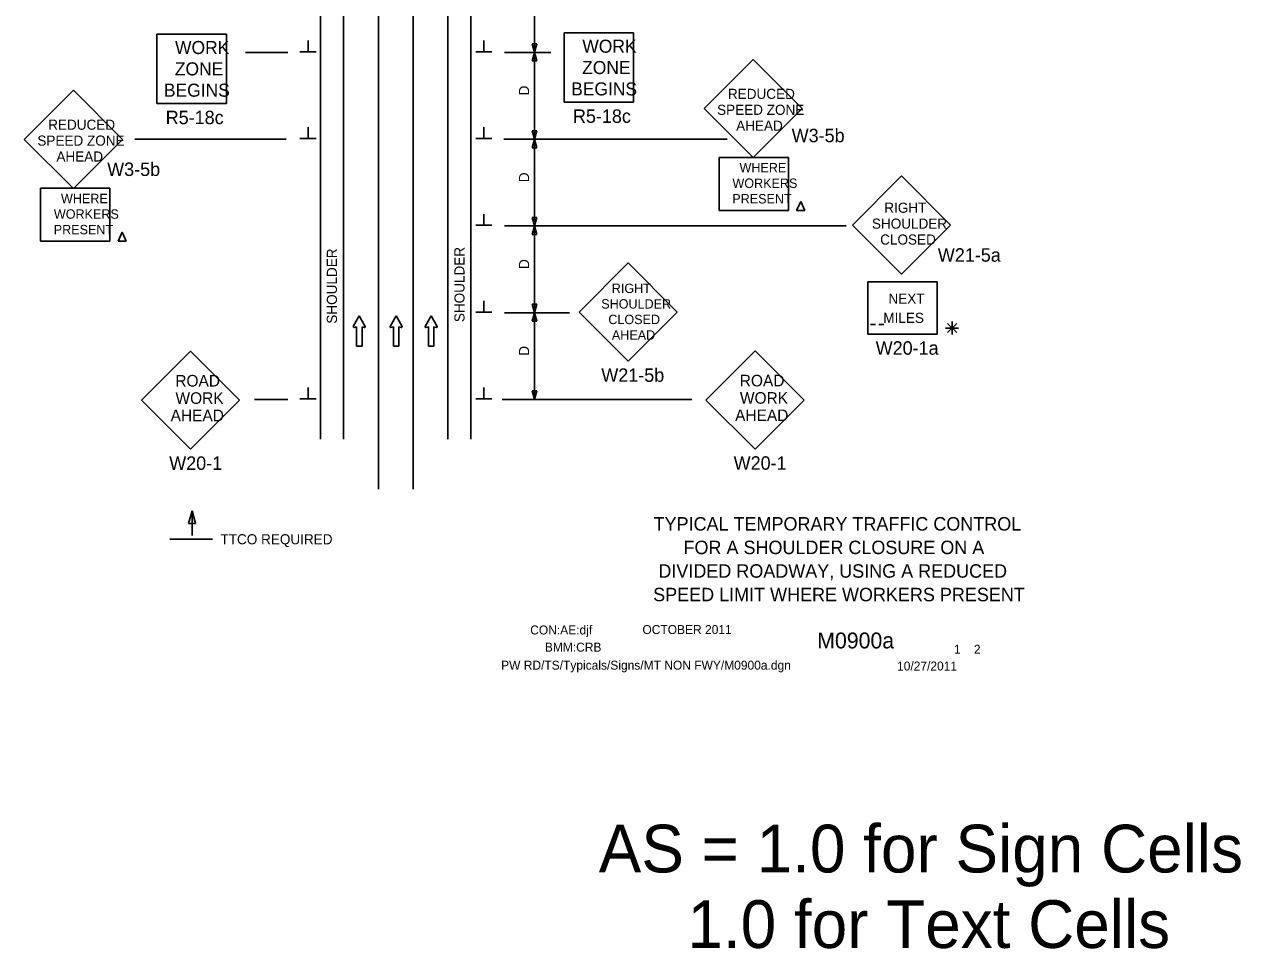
# Model space of a CAD drawing. Extents: x 16730 to 18471, y 7027 to 8225.
# Drawn here: x 16741 to 17582, y 7027 to 7666 of the extents above; entities that cross this region are included whole.
import ezdxf

# ---------------------------------------------------------------- set-up
doc = ezdxf.new("R2010")
doc.units = 0
for name, color, linetype in [('ALI_LEGAL_EX', 7, 'Continuous'), ('BORDER', 7, 'Continuous'), ('BORDER_SIGNAL_WO', 7, 'Continuous'), ('MT_SCRATCH_LEVEL_E', 7, 'Continuous'), ('PAVT_EDGE_EX', 7, 'Continuous'), ('TRAFFIC_SIGNS_PR', 7, 'Continuous'), ('TYPICAL_TEXT_DIMEN_PR', 7, 'Continuous')]:
    doc.layers.add(name, color=color, linetype=linetype)

msp = doc.modelspace()

# ---------------------------------------------------------------- linework, layer by layer
at = {"layer": 'ALI_LEGAL_EX'}
for points in [[(16985.65, 7625.29), (16985.65, 7600.29)], [(17009.65, 7625.29), (17009.65, 7600.29)], [(16985.65, 7525.29), (16985.65, 7500.29)], [(17009.65, 7525.29), (17009.65, 7500.29)], [(16985.65, 7425.29), (16985.65, 7400.29)], [(17009.65, 7425.29), (17009.65, 7400.29)]]:
    msp.add_lwpolyline(points, dxfattribs=at)
at = {"layer": 'MT_SCRATCH_LEVEL_E'}
for p, q in [((16972.46, 7464.59), (16968.34, 7457.35)), ((16972.46, 7464.59), (16968.34, 7457.35)), ((16976.6, 7457.35), (16972.46, 7464.59)), ((16976.6, 7457.35), (16972.46, 7464.59)), ((16997.88, 7464.59), (16993.77, 7457.35)), ((16997.88, 7464.59), (16993.77, 7457.35)), ((17002.03, 7457.35), (16997.88, 7464.59)), ((17002.03, 7457.35), (16997.88, 7464.59)), ((17022.09, 7464.59), (17017.98, 7457.35)), ((17022.09, 7464.59), (17017.98, 7457.35)), ((17026.24, 7457.35), (17022.09, 7464.59)), ((17026.24, 7457.35), (17022.09, 7464.59)), ((16968.83, 7456.67), (16970.6, 7456.99)), ((16968.83, 7456.67), (16970.6, 7456.99)), ((16970.6, 7456.99), (16970.6, 7443.73)), ((16970.6, 7456.99), (16970.6, 7443.73)), ((16974.35, 7443.73), (16974.35, 7456.99)), ((16974.35, 7456.99), (16976.12, 7456.67)), ((16974.35, 7443.73), (16974.35, 7456.99)), ((16974.35, 7456.99), (16976.12, 7456.67)), ((16994.25, 7456.67), (16996.03, 7456.99)), ((16994.25, 7456.67), (16996.03, 7456.99)), ((16996.03, 7456.99), (16996.03, 7443.73)), ((16996.03, 7456.99), (16996.03, 7443.73)), ((16999.77, 7443.73), (16999.77, 7456.99)), ((16999.77, 7456.99), (17001.55, 7456.67)), ((16999.77, 7443.73), (16999.77, 7456.99)), ((16999.77, 7456.99), (17001.55, 7456.67)), ((17018.47, 7456.67), (17020.24, 7456.99)), ((17018.47, 7456.67), (17020.24, 7456.99)), ((17020.24, 7456.99), (17020.24, 7443.73)), ((17020.24, 7456.99), (17020.24, 7443.73)), ((17023.98, 7443.73), (17023.98, 7456.99)), ((17023.98, 7456.99), (17025.76, 7456.67)), ((17023.98, 7443.73), (17023.98, 7456.99)), ((17023.98, 7456.99), (17025.76, 7456.67)), ((16970.6, 7443.73), (16974.35, 7443.73)), ((16970.6, 7443.73), (16974.35, 7443.73)), ((16996.03, 7443.73), (16999.77, 7443.73)), ((16996.03, 7443.73), (16999.77, 7443.73)), ((17020.24, 7443.73), (17023.98, 7443.73)), ((17020.24, 7443.73), (17023.98, 7443.73))]:
    msp.add_line(p, q, dxfattribs=at)
for centre, start, end in [((16968.75, 7457.13), 150.42484, 279.96381), ((16968.75, 7457.13), 150.42484, 279.96381), ((16976.19, 7457.13), 260.03619, 29.77312), ((16976.19, 7457.13), 260.03619, 29.77312), ((16994.18, 7457.13), 150.42484, 279.96381), ((16994.18, 7457.13), 150.42484, 279.96381), ((17001.62, 7457.13), 260.03619, 29.77312), ((17001.62, 7457.13), 260.03619, 29.77312), ((17018.39, 7457.13), 150.42484, 279.96381), ((17018.39, 7457.13), 150.42484, 279.96381), ((17025.83, 7457.13), 260.03619, 29.77312), ((17025.83, 7457.13), 260.03619, 29.77312)]:
    msp.add_arc(centre, 0.463, start, end, dxfattribs=at)
at = {"layer": 'PAVT_EDGE_EX'}
for p, q in [((16985.65, 8211.96), (16985.65, 7344.79)), ((17009.65, 8211.96), (17009.65, 7344.79)), ((16985.65, 8097.28), (16985.65, 7344.79)), ((17009.65, 8097.28), (17009.65, 7344.79)), ((16945.65, 7942.5), (16945.65, 7379.34)), ((16961.65, 7942.41), (16961.65, 7379.34)), ((17033.65, 7942.16), (17033.65, 7379.34)), ((17049.65, 7942.41), (17049.65, 7379.34))]:
    msp.add_line(p, q, dxfattribs=at)
at = {"layer": 'TRAFFIC_SIGNS_PR'}
for p, q in [((16832.54, 7611.53), (16832.54, 7659.53)), ((16832.54, 7659.53), (16880.54, 7659.53)), ((16880.54, 7611.53), (16880.54, 7659.53)), ((17114.22, 7612.43), (17114.22, 7660.43)), ((17114.22, 7660.43), (17162.22, 7660.43)), ((17162.22, 7612.43), (17162.22, 7660.43)), ((17244.86, 7641.98), (17210.92, 7608.04)), ((17278.8, 7608.04), (17244.86, 7641.98)), ((16774.73, 7620.67), (16740.79, 7586.73)), ((16808.67, 7586.73), (16774.73, 7620.67)), ((16832.54, 7611.53), (16880.54, 7611.53)), ((17114.22, 7612.43), (17162.22, 7612.43)), ((17210.92, 7608.04), (17244.86, 7574.1)), ((17244.86, 7574.1), (17278.8, 7608.04)), ((16740.79, 7586.73), (16774.73, 7552.79)), ((16774.73, 7552.79), (16808.67, 7586.73)), ((17221.31, 7574.28), (17269.31, 7574.28)), ((17221.31, 7537.63), (17221.31, 7574.28)), ((17269.31, 7537.63), (17269.31, 7574.28)), ((17347.53, 7561.43), (17313.59, 7527.48)), ((17381.47, 7527.48), (17347.53, 7561.43)), ((16752, 7552.95), (16800, 7552.95)), ((16752, 7516.31), (16752, 7552.95)), ((16800, 7516.31), (16800, 7552.95)), ((17221.31, 7537.63), (17269.31, 7537.63)), ((17313.59, 7527.48), (17347.53, 7493.54)), ((17347.53, 7493.54), (17381.47, 7527.48)), ((16752, 7516.31), (16800, 7516.31)), ((17158.42, 7501.21), (17124.48, 7467.27)), ((17192.36, 7467.27), (17158.42, 7501.21)), ((17324.19, 7452.07), (17324.19, 7488.07)), ((17324.19, 7488.07), (17372.19, 7488.07)), ((17372.19, 7452.07), (17372.19, 7488.07)), ((17124.48, 7467.27), (17158.42, 7433.33)), ((17158.42, 7433.33), (17192.36, 7467.27)), ((17326.04, 7458.67), (17329.54, 7458.67)), ((17331.84, 7458.67), (17335.34, 7458.67)), ((17324.19, 7452.07), (17372.19, 7452.07)), ((16855.78, 7440.31), (16821.84, 7406.37)), ((16889.72, 7406.37), (16855.78, 7440.31)), ((17246.17, 7440.4), (17212.23, 7406.45)), ((17280.12, 7406.45), (17246.17, 7440.4)), ((16821.84, 7406.37), (16855.78, 7372.42)), ((16855.78, 7372.42), (16889.72, 7406.37)), ((17212.23, 7406.45), (17246.17, 7372.51)), ((17246.17, 7372.51), (17280.12, 7406.45))]:
    msp.add_line(p, q, dxfattribs=at)
for points in [[(17277.74, 7543.8), (17274.95, 7537.63)], [(17274.95, 7537.63), (17277.74, 7543.8)], [(17280.54, 7537.63), (17277.74, 7543.8)], [(17277.74, 7543.8), (17280.54, 7537.63)], [(17274.95, 7537.63), (17280.54, 7537.63)], [(17280.54, 7537.63), (17274.95, 7537.63)], [(16808.44, 7522.48), (16805.64, 7516.31)], [(16805.64, 7516.31), (16808.44, 7522.48)], [(16811.23, 7516.31), (16808.44, 7522.48)], [(16808.44, 7522.48), (16811.23, 7516.31)], [(16805.64, 7516.31), (16811.23, 7516.31)], [(16811.23, 7516.31), (16805.64, 7516.31)]]:
    msp.add_lwpolyline(points, dxfattribs=at)
at = {"layer": 'TYPICAL_TEXT_DIMEN_PR'}
for p, q in [((17093.65, 7706.83), (17093.65, 7646.83)), ((16942.65, 7647.26), (16931.4, 7647.26)), ((16937.02, 7647.26), (16937.02, 7655.05)), ((17064.21, 7647.26), (17052.96, 7647.26)), ((17058.58, 7647.26), (17058.58, 7655.05)), ((17093.65, 7646.83), (17092.08, 7652.7)), ((17092.08, 7652.7), (17093.65, 7652.7)), ((17093.65, 7652.7), (17095.22, 7652.7)), ((17095.22, 7652.7), (17093.65, 7646.83)), ((16893.76, 7646.83), (16923.12, 7646.83)), ((17072.81, 7646.83), (17104.89, 7646.83)), ((17092.08, 7640.97), (17093.65, 7646.83)), ((17093.65, 7640.97), (17092.08, 7640.97)), ((17093.65, 7646.83), (17093.65, 7586.83)), ((17093.65, 7646.83), (17095.22, 7640.97)), ((17095.22, 7640.97), (17093.65, 7640.97)), ((16937.02, 7587.26), (16937.02, 7595.05)), ((17058.58, 7587.26), (17058.58, 7595.05)), ((17093.65, 7586.83), (17092.08, 7592.7)), ((17092.08, 7592.7), (17093.65, 7592.7)), ((17093.65, 7592.7), (17095.22, 7592.7)), ((17095.22, 7592.7), (17093.65, 7586.83)), ((16817.21, 7586.83), (16921.99, 7586.83)), ((16942.65, 7587.26), (16931.4, 7587.26)), ((17064.21, 7587.26), (17052.96, 7587.26)), ((17072.33, 7586.83), (17226.79, 7586.83)), ((17092.08, 7580.97), (17093.65, 7586.83)), ((17093.65, 7580.97), (17092.08, 7580.97)), ((17093.65, 7586.83), (17093.65, 7526.83)), ((17093.65, 7586.83), (17095.22, 7580.97)), ((17095.22, 7580.97), (17093.65, 7580.97)), ((17058.58, 7527.26), (17058.58, 7535.05)), ((17093.65, 7526.83), (17092.08, 7532.7)), ((17092.08, 7532.7), (17093.65, 7532.7)), ((17093.65, 7532.7), (17095.22, 7532.7)), ((17095.22, 7532.7), (17093.65, 7526.83)), ((17064.21, 7527.26), (17052.96, 7527.26)), ((17072.81, 7526.83), (17309.15, 7526.83)), ((17092.08, 7520.97), (17093.65, 7526.83)), ((17093.65, 7520.97), (17092.08, 7520.97)), ((17093.65, 7526.83), (17093.65, 7466.83)), ((17093.65, 7526.83), (17095.22, 7520.97)), ((17095.22, 7520.97), (17093.65, 7520.97)), ((17058.58, 7467.26), (17058.58, 7475.05)), ((17093.65, 7466.83), (17092.08, 7472.7)), ((17092.08, 7472.7), (17093.65, 7472.7)), ((17093.65, 7472.7), (17095.22, 7472.7)), ((17095.22, 7472.7), (17093.65, 7466.83)), ((17064.21, 7467.26), (17052.96, 7467.26)), ((17072.81, 7466.83), (17117.89, 7466.83)), ((17092.08, 7460.97), (17093.65, 7466.83)), ((17093.65, 7466.83), (17093.65, 7406.83)), ((17093.65, 7466.83), (17095.22, 7460.97)), ((17093.65, 7460.97), (17092.08, 7460.97)), ((17095.22, 7460.97), (17093.65, 7460.97)), ((17382.47, 7456.22), (17377.94, 7456.22)), ((17379.28, 7459.41), (17385.66, 7453.03)), ((17385.66, 7459.41), (17379.28, 7453.03)), ((17382.47, 7456.22), (17382.47, 7460.67)), ((17382.47, 7456.22), (17385.66, 7456.22)), ((17382.47, 7456.22), (17386.95, 7456.22)), ((17382.47, 7456.22), (17382.47, 7451.72)), ((16937.02, 7407.26), (16937.02, 7415.05)), ((17058.58, 7407.26), (17058.58, 7415.05)), ((17093.65, 7406.83), (17092.08, 7412.7)), ((17092.08, 7412.7), (17093.65, 7412.7)), ((17093.65, 7412.7), (17095.22, 7412.7)), ((17095.22, 7412.7), (17093.65, 7406.83)), ((16899.92, 7406.83), (16923.12, 7406.83)), ((16942.65, 7407.26), (16931.4, 7407.26)), ((17064.21, 7407.26), (17052.96, 7407.26)), ((17071.2, 7406.83), (17202.52, 7406.83)), ((16854.42, 7321.08), (16856.77, 7329.88)), ((16856.77, 7312.75), (16856.77, 7329.88)), ((16856.77, 7329.88), (16859.13, 7321.08)), ((16856.77, 7321.08), (16854.42, 7321.08)), ((16859.13, 7321.08), (16856.77, 7321.08)), ((16870.95, 7310.25), (16841.51, 7310.25))]:
    msp.add_line(p, q, dxfattribs=at)

# ---------------------------------------------------------------- texts
at = {"layer": 'BORDER'}
for s, p in [('TYPICAL TEMPORARY TRAFFIC CONTROL', (17176.01, 7316.16)), ('FOR A SHOULDER CLOSURE ON A', (17196.72, 7299.86)), ('DIVIDED ROADWAY, USING A REDUCED', (17179.33, 7283.56)), ('SPEED LIMIT WHERE WORKERS PRESENT', (17175.72, 7267.26))]:
    msp.add_text(s, height=9.3, dxfattribs=at).set_placement(p)
at = {"layer": 'BORDER_SIGNAL_WO'}
for s, height, p in [('CON:AE:djf', 6.2, (17090.69, 7244.31)), ('    OCTOBER 2011    ', 6.2, (17159.08, 7244.59)), ('    M0900a   ', 11, (17272.86, 7234.63)), ('BMM:CRB   ', 6.2, (17100.81, 7232.42)), (' 1    2 ', 6.2, (17381.45, 7230.95)), ('PW RD/TS/Typicals/Signs/MT NON FWY/M0900a.dgn     ', 6.2, (17070.55, 7219.96)), ('10/27/2011    ', 6.2, (17344.4, 7219.38)), ('AS = 1.0 for Sign Cells', 33.0301, (17138.06, 7079.7)), ('     1.0 for Text Cells', 33.0301, (17138.06, 7027.47))]:
    msp.add_text(s, height=height, dxfattribs=at).set_placement(p)
at = {"layer": 'TRAFFIC_SIGNS_PR'}
for s, height, p in [('WORK', 9.021, (17126.73, 7646.64)), ('WORK', 9.021, (16845.04, 7645.73)), ('ZONE', 9.021, (16844.9, 7630.97)), ('ZONE', 9.021, (17126.58, 7631.88)), ('BEGINS', 9.021, (16837.31, 7616.21)), ('BEGINS', 9.021, (17118.99, 7617.11)), ('REDUCED', 7, (17227.43, 7614.67)), ('R5-18c', 9.3, (16838.56, 7597.23)), ('R5-18c', 9.3, (17120.24, 7598.13)), ('SPEED ZONE', 7, (17219.92, 7603.67)), ('REDUCED', 7, (16757.3, 7593.36)), ('AHEAD', 7, (17233.12, 7592.67)), ('SPEED ZONE', 7, (16749.79, 7582.36)), ('W3-5b', 9.3, (17271.51, 7584.74)), ('AHEAD', 7, (16762.99, 7571.36)), ('W3-5b', 9.3, (16798.09, 7561.39)), ('WHERE', 6.5, (17235.45, 7563.88)), ('WORKERS', 6.5, (17230.54, 7553.13)), ('WHERE', 6.5, (16766.14, 7542.56)), ('PRESENT', 6.5, (17230.45, 7542.38)), ('WORKERS', 6.5, (16761.23, 7531.81)), ('RIGHT', 7, (17335.59, 7535.94)), ('SHOULDER', 7, (17327.02, 7524.94)), ('PRESENT', 6.5, (16761.15, 7521.06)), ('CLOSED', 7, (17332.73, 7513.94)), ('W21-5a', 9.3, (17372.6, 7502.1)), ('RIGHT', 6.5, (17147.09, 7480.44)), ('NEXT', 7, (17338.44, 7473.08)), ('SHOULDER', 6.5, (17139.82, 7469.69)), ('CLOSED', 6.5, (17144.71, 7458.94)), ('   MILES', 7, (17327.1, 7459.78)), ('AHEAD', 6.5, (17147.16, 7448.19)), ('W20-1a', 9.3, (17329.61, 7437.77)), ('W21-5b', 9.3, (17139.86, 7419.03)), ('ROAD', 8, (16845.21, 7415.79)), ('ROAD', 8, (17235.6, 7415.88)), ('WORK', 8, (16845.34, 7403.79)), ('WORK', 8, (17235.74, 7403.88)), ('AHEAD', 8, (16841.98, 7391.79)), ('AHEAD', 8, (17232.38, 7391.88)), ('W20-1', 9.3, (16840.99, 7358.13)), ('W20-1', 9.3, (17231.39, 7358.22))]:
    msp.add_text(s, height=height, dxfattribs=at).set_placement(p)
at = {"layer": 'TYPICAL_TEXT_DIMEN_PR'}
for s, p in [('D', (17089.92, 7617.08)), ('D', (17089.92, 7557.08)), ('SHOULDER', (16957.01, 7459.24)), ('SHOULDER', (17045.24, 7460.3)), ('D', (17089.92, 7497.08)), ('D', (17089.92, 7437.08))]:
    msp.add_text(s, height=7, rotation=90, dxfattribs=at).set_placement(p)
msp.add_text('TTCO REQUIRED', height=7, dxfattribs=at).set_placement((16876.46, 7306.65))

doc.saveas('drawing.dxf')
